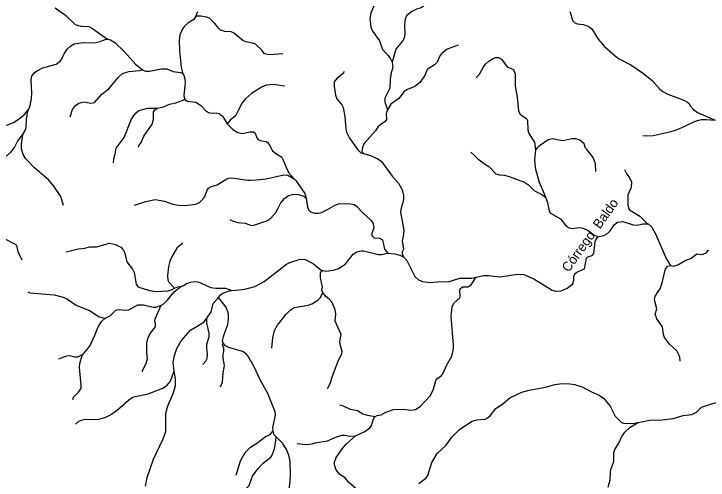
# Model space of a CAD drawing. Extents: x 473.9 to 500, y 7733.1 to 7760.8.
# Drawn here: x 487.72 to 494.97, y 7752.7 to 7757.57 of the extents above; entities that cross this region are included whole.
import ezdxf
from ezdxf.enums import TextEntityAlignment as Align

# ---------------------------------------------------------------- set-up
doc = ezdxf.new("R2010")
doc.units = 0
doc.header["$LTSCALE"] = 0.032
doc.layers.add('61', color=7, linetype='Continuous')
doc.layers.add('7', color=7, linetype='Continuous', lineweight=25)

msp = doc.modelspace()

# ---------------------------------------------------------------- linework, layer by layer
at = {"layer": '7'}
for points in [[(491.4328, 7757.94), (491.4295, 7757.9331), (491.4258, 7757.9254), (491.4287, 7757.8729), (491.4673, 7757.7937), (491.4875, 7757.7148), (491.481, 7757.6524), (491.4525, 7757.576), (491.4403, 7757.5199), (491.4523, 7757.4291), (491.4689, 7757.388), (491.5408, 7757.286), (491.5737, 7757.1962), (491.6292, 7757.1362), (491.653, 7757.1032), (491.6721, 7757.0618)], [(492.0601, 7757.6892), (491.9761, 7757.6316), (491.9275, 7757.6161), (491.8778, 7757.5911), (491.8233, 7757.5454), (491.8107, 7757.5127), (491.8042, 7757.4537), (491.8074, 7757.3614), (491.7987, 7757.3142), (491.7819, 7757.2829), (491.7129, 7757.1992), (491.6721, 7757.0618)], [(488.1564, 7757.6295), (488.2076, 7757.5922), (488.2622, 7757.5526), (488.3649, 7757.4568), (488.4241, 7757.4387), (488.5069, 7757.435), (488.5451, 7757.4161), (488.6674, 7757.3261), (488.7063, 7757.3039)], [(489.6379, 7757.5896), (489.636, 7757.5825), (489.6251, 7757.5419)], [(493.5277, 7757.5933), (493.561, 7757.4945), (493.5804, 7757.4738), (493.6057, 7757.4629), (493.6698, 7757.4565), (493.7198, 7757.4394), (493.7579, 7757.4112), (493.8247, 7757.3032), (493.8904, 7757.2251), (494.0045, 7757.126), (494.0454, 7757.097), (494.1642, 7757.0356), (494.2971, 7756.9448), (494.3878, 7756.8727), (494.468, 7756.7805), (494.5012, 7756.756), (494.5515, 7756.7299), (494.7189, 7756.6664), (494.7582, 7756.645), (494.7736, 7756.632), (494.7854, 7756.6081), (494.8159, 7756.5705), (494.8609, 7756.5353), (495.0451, 7756.4561)], [(489.6251, 7757.5419), (489.6033, 7757.5092), (489.5397, 7757.47), (489.5045, 7757.438), (489.4832, 7757.412), (489.455, 7757.348), (489.4494, 7757.2854), (489.4542, 7757.1797), (489.472, 7757.0096), (489.4873, 7756.9412)], [(490.5317, 7757.1489), (490.3917, 7757.14), (490.3552, 7757.1449), (490.3362, 7757.1537), (490.3155, 7757.1846), (490.2465, 7757.2502), (490.2146, 7757.2623), (490.1468, 7757.2752), (490.1127, 7757.2905), (490.0162, 7757.3684), (489.9938, 7757.3796), (489.9261, 7757.3845), (489.8822, 7757.3988), (489.8588, 7757.4182), (489.8236, 7757.4665), (489.766, 7757.5216), (489.7341, 7757.5344), (489.6756, 7757.5449), (489.6665, 7757.5444), (489.6251, 7757.5419)], [(487.8783, 7756.5705), (487.8933, 7756.609), (487.9075, 7756.685), (487.9107, 7756.7378), (487.9029, 7756.8789), (487.9125, 7756.9165), (487.9402, 7756.9537), (487.9653, 7756.9739), (488.0243, 7757.0027), (488.1654, 7757.042), (488.2072, 7757.0732), (488.2251, 7757.0971), (488.2473, 7757.1498), (488.2801, 7757.1982), (488.3194, 7757.2342), (488.3533, 7757.2554), (488.446, 7757.2682), (488.5614, 7757.2652), (488.6231, 7757.2775), (488.6784, 7757.3012), (488.7063, 7757.3039)], [(488.7063, 7757.3039), (488.7317, 7757.2978), (488.7786, 7757.268), (488.8793, 7757.1696), (488.9942, 7757.041), (489.0664, 7756.9839)], [(492.3631, 7757.2403), (492.2485, 7757.1976), (492.188, 7757.1501), (492.1701, 7757.1304), (492.1437, 7757.0639), (492.1151, 7757.0362), (492.0401, 7756.9847), (492.0155, 7756.9236), (491.9635, 7756.8511), (491.9118, 7756.807), (491.8344, 7756.779), (491.8007, 7756.7561), (491.7424, 7756.6829), (491.6582, 7756.6231), (491.6212, 7756.5564)], [(491.6721, 7757.0618), (491.6799, 7757.0055), (491.664, 7756.9502), (491.6535, 7756.8836), (491.6496, 7756.7918), (491.598, 7756.6874), (491.5974, 7756.6453), (491.619, 7756.5891), (491.6212, 7756.5564)], [(492.5492, 7756.8988), (492.5865, 7756.9373), (492.6286, 7757.0127), (492.6531, 7757.0443), (492.6835, 7757.0748), (492.7269, 7757.1026), (492.7519, 7757.1102), (492.7837, 7757.1103), (492.815, 7757.0952), (492.876, 7757.0143), (492.9391, 7756.9862), (492.9579, 7756.9387), (492.9588, 7756.8114), (492.9805, 7756.6975), (492.9926, 7756.555), (493.0059, 7756.5244), (493.031, 7756.5012), (493.075, 7756.476), (493.0862, 7756.4528), (493.0911, 7756.3556), (493.0995, 7756.3175), (493.1608, 7756.2267), (493.1703, 7756.1458)], [(489.0664, 7756.9839), (489.0975, 7756.9701), (489.1389, 7756.9687), (489.2622, 7756.9916), (489.3201, 7756.9918), (489.3857, 7756.9668), (489.4627, 7756.9532), (489.4873, 7756.9412)], [(488.3098, 7756.4908), (488.3348, 7756.5696), (488.3658, 7756.6115), (488.4009, 7756.6349), (488.4578, 7756.6485), (488.5287, 7756.6357), (488.5648, 7756.642), (488.6417, 7756.7284), (488.7139, 7756.7845), (488.8117, 7756.9016), (488.8595, 7756.9448), (488.9236, 7756.9666), (489.037, 7756.9754), (489.0664, 7756.9839)], [(489.4873, 7756.9412), (489.4996, 7756.9278), (489.5096, 7756.8887), (489.5111, 7756.8499), (489.4987, 7756.7156), (489.4982, 7756.7104), (489.5101, 7756.6735)], [(491.17, 7756.9652), (491.1661, 7756.9481), (491.0984, 7756.8944), (491.0687, 7756.8563), (491.0666, 7756.8133), (491.0819, 7756.7171), (491.0956, 7756.6814), (491.1489, 7756.6167), (491.1632, 7756.5876), (491.1804, 7756.493), (491.1884, 7756.3713), (491.198, 7756.3312), (491.2292, 7756.2695), (491.3148, 7756.146), (491.3456, 7756.1162), (491.3766, 7756.1093)], [(490.5505, 7756.8123), (490.4353, 7756.8296), (490.3613, 7756.8233), (490.3178, 7756.8064), (490.2044, 7756.7354), (490.1417, 7756.6808), (490.1088, 7756.639), (490.0633, 7756.5507), (490.0391, 7756.5039), (489.9838, 7756.4573), (489.9512, 7756.4186)], [(489.2203, 7756.5818), (489.2875, 7756.5978), (489.3481, 7756.6241), (489.413, 7756.6371), (489.5101, 7756.6735)], [(489.5101, 7756.6735), (489.5329, 7756.6558), (489.6234, 7756.6458), (489.6733, 7756.6121), (489.723, 7756.5584), (489.756, 7756.537), (489.7862, 7756.5315), (489.8354, 7756.5346), (489.8673, 7756.5256), (489.9007, 7756.4986), (489.9512, 7756.4186)], [(487.5421, 7756.3323), (487.5839, 7756.3541), (487.6324, 7756.397), (487.725, 7756.4345), (487.7822, 7756.4727), (487.8302, 7756.5142), (487.8783, 7756.5705)], [(487.818, 7756.3076), (487.8393, 7756.3437), (487.8507, 7756.3813), (487.855, 7756.4629), (487.8687, 7756.5547), (487.8783, 7756.5705)], [(488.7655, 7756.0124), (488.7663, 7756.057), (488.7815, 7756.1016), (488.7925, 7756.1652), (488.876, 7756.2754), (488.9472, 7756.4595), (488.9757, 7756.5068), (488.9991, 7756.5342), (489.0301, 7756.5562), (489.0801, 7756.5735), (489.1203, 7756.5827), (489.2203, 7756.5818)], [(489.0243, 7756.1755), (489.0279, 7756.1896), (489.0519, 7756.2226), (489.0794, 7756.2896), (489.1682, 7756.4165), (489.1807, 7756.4634), (489.1811, 7756.5437), (489.1922, 7756.5627), (489.2203, 7756.5818)], [(491.6212, 7756.5564), (491.6101, 7756.5274), (491.6148, 7756.4649), (491.6014, 7756.4435), (491.5288, 7756.3905), (491.4993, 7756.3467), (491.3811, 7756.2142), (491.3624, 7756.1719), (491.3585, 7756.1337), (491.3646, 7756.1178), (491.3766, 7756.1093)], [(489.9512, 7756.4186), (490.0109, 7756.358), (490.0634, 7756.3284), (490.1133, 7756.3182), (490.1866, 7756.3342), (490.2047, 7756.3345), (490.225, 7756.3349), (490.244, 7756.3226), (490.2619, 7756.2726), (490.2753, 7756.2541), (490.2943, 7756.2442), (490.3578, 7756.2339), (490.3693, 7756.2254), (490.3884, 7756.2023), (490.4249, 7756.1355), (490.4542, 7756.1109), (490.5204, 7756.0711), (490.5909, 7755.9117), (490.6489, 7755.8457)], [(494.2915, 7756.2975), (494.3194, 7756.2933), (494.399, 7756.2973), (494.5887, 7756.3391), (494.6419, 7756.3556), (494.7282, 7756.3955), (494.8372, 7756.4459), (494.9032, 7756.4639), (494.9549, 7756.4649), (495.0451, 7756.4561)], [(487.2806, 7755.6013), (487.308, 7755.6357), (487.3764, 7755.6837), (487.401, 7755.7106), (487.4524, 7755.8173), (487.5289, 7755.9153), (487.5856, 7756.0111), (487.6355, 7756.0725), (487.6956, 7756.1271), (487.7287, 7756.1707), (487.7652, 7756.2421), (487.818, 7756.3076)], [(488.2419, 7755.565), (488.2135, 7755.6605), (488.1402, 7755.7689), (488.0853, 7755.8324), (487.9389, 7755.958), (487.8455, 7756.0566), (487.8206, 7756.0977), (487.8018, 7756.1566), (487.8018, 7756.2074), (487.818, 7756.3076)], [(493.8019, 7755.9224), (493.7965, 7755.9997), (493.7721, 7756.0657), (493.7048, 7756.1514), (493.6941, 7756.165), (493.677, 7756.2113), (493.6348, 7756.2464), (493.5961, 7756.2634), (493.5498, 7756.2635), (493.4569, 7756.2428), (493.3945, 7756.2531), (493.3503, 7756.2604), (493.3023, 7756.2524), (493.2211, 7756.1959), (493.1883, 7756.1691), (493.1703, 7756.1458)], [(492.4961, 7756.122), (492.536, 7756.0834), (492.5667, 7756.0537), (492.6487, 7755.9922), (492.6835, 7755.9727), (492.7578, 7755.8979), (492.7917, 7755.8868), (492.8484, 7755.8811), (492.8959, 7755.8692), (493.0566, 7755.8105), (493.0963, 7755.7813), (493.1587, 7755.7188), (493.2381, 7755.6814), (493.2737, 7755.6513)], [(493.1703, 7756.1458), (493.1593, 7756.0427), (493.1653, 7755.9655), (493.1708, 7755.945), (493.184, 7755.8953), (493.2071, 7755.8089), (493.2553, 7755.7058), (493.2737, 7755.6513)], [(491.3766, 7756.1093), (491.4479, 7756.0873), (491.5246, 7756.0531), (491.5623, 7756.0236), (491.6744, 7755.8726), (491.7414, 7755.8004), (491.7784, 7755.7299), (491.7929, 7755.6739), (491.7913, 7755.6313), (491.785, 7755.592), (491.7826, 7755.5848), (491.7626, 7755.5246), (491.761, 7755.4949), (491.7962, 7755.3069), (491.7936, 7755.2638), (491.7786, 7755.1979), (491.7906, 7755.1078), (491.7778, 7755.0822), (491.7794, 7755.0588), (491.7952, 7755.0267)], [(494.1014, 7755.9421), (494.1243, 7755.8938), (494.1566, 7755.8522), (494.1719, 7755.8123), (494.1695, 7755.7524), (494.1342, 7755.6767), (494.1358, 7755.5689), (494.1452, 7755.5314), (494.1508, 7755.5205), (494.2595, 7755.4552), (494.3393, 7755.3745)], [(488.9829, 7755.5679), (489.1006, 7755.6085), (489.2002, 7755.6286), (489.2959, 7755.6094), (489.3825, 7755.5797), (489.4416, 7755.5707), (489.509, 7755.5669), (489.6227, 7755.5803), (489.6611, 7755.598), (489.6984, 7755.6308), (489.717, 7755.6604), (489.7417, 7755.7274), (489.7568, 7755.745), (489.7868, 7755.7627), (489.8469, 7755.7812), (489.9475, 7755.8443), (489.9669, 7755.8499), (489.9995, 7755.853), (490.1663, 7755.8307), (490.1937, 7755.8312), (490.2542, 7755.8323), (490.3597, 7755.8443), (490.5416, 7755.885), (490.5851, 7755.884), (490.6489, 7755.8457)], [(490.6489, 7755.8457), (490.6663, 7755.8258), (490.7615, 7755.6902), (490.7762, 7755.6408)], [(489.9783, 7755.4186), (490.0119, 7755.4007), (490.0624, 7755.3881), (490.139, 7755.3816), (490.2049, 7755.3576), (490.23, 7755.3598), (490.3652, 7755.4055), (490.4065, 7755.4343), (490.4602, 7755.4914), (490.4859, 7755.543), (490.5103, 7755.592), (490.5491, 7755.6371), (490.5906, 7755.6683), (490.6477, 7755.6831), (490.6958, 7755.68), (490.752, 7755.663), (490.7762, 7755.6408)], [(490.7762, 7755.6408), (490.7881, 7755.5476), (490.8028, 7755.5174), (490.8202, 7755.5006), (490.861, 7755.4859), (490.9002, 7755.4859), (490.9371, 7755.4935), (491.0002, 7755.5232), (491.07, 7755.5654), (491.1211, 7755.5861), (491.2369, 7755.5844), (491.2753, 7755.5747), (491.3005, 7755.5598), (491.3693, 7755.4838), (491.4501, 7755.4111), (491.4755, 7755.3787), (491.4802, 7755.3457), (491.4819, 7755.3339), (491.4627, 7755.2714), (491.4627, 7755.2505), (491.4869, 7755.227), (491.54, 7755.2228), (491.5716, 7755.2082), (491.5948, 7755.1077), (491.6291, 7755.0664)], [(493.2737, 7755.6513), (493.292, 7755.6077), (493.3178, 7755.4974), (493.3266, 7755.4846), (493.4321, 7755.4278), (493.4797, 7755.3627), (493.5009, 7755.3452), (493.5219, 7755.3326), (493.5565, 7755.3256), (493.6249, 7755.3367), (493.6672, 7755.3288), (493.7188, 7755.3038), (493.7804, 7755.2594), (493.8258, 7755.2399)], [(487.809, 7754.9939), (487.7694, 7755.083), (487.7589, 7755.1332), (487.7472, 7755.1538), (487.6124, 7755.2226), (487.5339, 7755.3268), (487.5145, 7755.3444), (487.4295, 7755.3946), (487.3523, 7755.4254), (487.3051, 7755.4693), (487.2734, 7755.5272), (487.2806, 7755.6013)], [(493.8258, 7755.2399), (493.8853, 7755.2524), (493.9236, 7755.2738), (493.9508, 7755.3024), (493.9944, 7755.3662), (494.0268, 7755.3904), (494.0812, 7755.3984), (494.1912, 7755.365), (494.2305, 7755.361), (494.2929, 7755.3752), (494.3393, 7755.3745)], [(494.3393, 7755.3745), (494.3479, 7755.3726), (494.3841, 7755.3386), (494.4276, 7755.2629), (494.5362, 7755.013), (494.5792, 7754.9397)], [(489.4834, 7755.1763), (489.4732, 7755.1601), (489.426, 7755.1184), (489.3795, 7755.0415), (489.3527, 7754.985), (489.3365, 7754.9268), (489.3283, 7754.8296), (489.3327, 7754.7841), (489.3424, 7754.766), (489.4012, 7754.7008)], [(492.5497, 7754.8163), (492.6284, 7754.8332), (492.6801, 7754.8332), (492.7932, 7754.8204), (492.8237, 7754.825), (492.9837, 7754.8492), (493.0497, 7754.8457), (493.1519, 7754.8008), (493.3459, 7754.6805), (493.3825, 7754.669), (493.4369, 7754.6751), (493.5003, 7754.7007), (493.562, 7754.7456), (493.5721, 7754.7848), (493.5706, 7754.824), (493.5811, 7754.8501), (493.602, 7754.8677), (493.6834, 7754.9031), (493.7016, 7755.0164), (493.7169, 7755.0305), (493.7623, 7755.0427), (493.7811, 7755.0645), (493.795, 7755.1889), (493.8049, 7755.2151), (493.8258, 7755.2399)], [(488.2689, 7755.0806), (488.3938, 7755.1123), (488.4661, 7755.12), (488.515, 7755.1339), (488.5861, 7755.1348), (488.7218, 7755.1715), (488.7842, 7755.1592), (488.8414, 7755.131), (488.8655, 7755.1022), (488.8781, 7755.0774), (488.9023, 7754.9757), (488.9615, 7754.8995), (488.9802, 7754.8656), (489.0017, 7754.7425), (489.0138, 7754.7212), (489.0274, 7754.7107), (489.1404, 7754.6769), (489.2092, 7754.6681), (489.3363, 7754.6752), (489.3761, 7754.6864), (489.4012, 7754.7008)], [(494.5792, 7754.9397), (494.6157, 7754.9311), (494.6563, 7754.9459), (494.7417, 7754.995), (494.7929, 7755.0111), (494.8564, 7755.0591), (494.9074, 7755.0547), (494.9575, 7755.0697), (494.978, 7755.103)], [(490.9494, 7754.885), (490.9845, 7754.8806), (491.0575, 7754.8885), (491.105, 7754.9053), (491.1579, 7754.9336), (491.1898, 7754.9589), (491.2653, 7755.0559), (491.305, 7755.0829), (491.3489, 7755.0923), (491.3741, 7755.0907), (491.5309, 7755.053), (491.5624, 7755.0522), (491.6291, 7755.0664)], [(491.6291, 7755.0664), (491.7032, 7755.0609), (491.7549, 7755.0472), (491.7952, 7755.0267)], [(489.9983, 7754.6785), (490.1123, 7754.6898), (490.1369, 7754.6922), (490.2403, 7754.7191), (490.3356, 7754.7718), (490.5712, 7754.9514), (490.605, 7754.9704), (490.7118, 7755.004), (490.7642, 7755.0006), (490.8151, 7754.9782), (490.854, 7754.9563), (490.9335, 7754.8916), (490.9494, 7754.885)], [(491.7952, 7755.0267), (491.827, 7754.9913), (491.9121, 7754.8222), (491.9483, 7754.7877), (491.9902, 7754.7706), (492.075, 7754.7626), (492.1814, 7754.7722), (492.26, 7754.7691), (492.3787, 7754.806), (492.5072, 7754.806), (492.5497, 7754.8163)], [(494.6827, 7753.941), (494.6791, 7753.986), (494.6479, 7754.0477), (494.5714, 7754.1178), (494.5174, 7754.1853), (494.5054, 7754.219), (494.4964, 7754.2979), (494.4387, 7754.3821), (494.4213, 7754.4304), (494.4371, 7754.4853), (494.4141, 7754.5795), (494.4198, 7754.619), (494.4596, 7754.6766), (494.4725, 7754.6953), (494.4941, 7754.7562), (494.5294, 7754.9039), (494.5516, 7754.9331), (494.5792, 7754.9397)], [(490.95, 7754.6565), (490.941, 7754.6818), (490.9478, 7754.7128), (490.9256, 7754.8101), (490.9253, 7754.8612), (490.9302, 7754.8714), (490.9494, 7754.885)], [(491.4958, 7753.3604), (491.5175, 7753.3707), (491.5604, 7753.3791), (491.6077, 7753.4052), (491.6871, 7753.4349), (491.7865, 7753.4381), (491.8686, 7753.4285), (491.918, 7753.4342), (491.9656, 7753.4656), (492.0713, 7753.5788), (492.1023, 7753.635), (492.128, 7753.7361), (492.1397, 7753.7533), (492.184, 7753.7852), (492.2035, 7753.8065), (492.2456, 7753.9009), (492.298, 7753.991), (492.3141, 7754.0676), (492.3157, 7754.1081), (492.2901, 7754.4077), (492.3016, 7754.5116), (492.3209, 7754.5474), (492.3799, 7754.6022), (492.3847, 7754.6215), (492.3799, 7754.6709), (492.3834, 7754.6947), (492.4077, 7754.7154), (492.4645, 7754.7169), (492.4983, 7754.7354), (492.5497, 7754.8163)], [(489.4657, 7754.721), (489.4957, 7754.7312), (489.5342, 7754.7533), (489.5708, 7754.7659), (489.6108, 7754.7707), (489.6401, 7754.7665), (489.6667, 7754.7601), (489.737, 7754.7259), (489.7815, 7754.7099), (489.8339, 7754.7026), (489.9325, 7754.7026), (489.9983, 7754.6785)], [(489.2619, 7754.5231), (489.2782, 7754.5301), (489.3286, 7754.5769), (489.3978, 7754.663), (489.4657, 7754.721)], [(489.4012, 7754.7008), (489.4355, 7754.7168), (489.4657, 7754.721)], [(489.8606, 7754.6054), (489.881, 7754.6321), (489.9065, 7754.6485), (489.975, 7754.6753), (489.9983, 7754.6785)], [(487.8696, 7754.6643), (487.8895, 7754.6545), (488.1439, 7754.631), (488.2384, 7754.6075), (488.2844, 7754.587), (488.3743, 7754.5261), (488.5195, 7754.4648), (488.6064, 7754.4076), (488.641, 7754.3945), (488.6757, 7754.3897)], [(489.7373, 7754.3874), (489.7847, 7754.455), (489.804, 7754.5402), (489.8606, 7754.6054)], [(489.9082, 7754.1267), (489.9035, 7754.149), (489.912, 7754.1979), (489.9376, 7754.2661), (489.9381, 7754.2675), (489.9586, 7754.3221), (489.9649, 7754.3775), (489.9633, 7754.4336), (489.9392, 7754.5045), (489.8606, 7754.6054)], [(490.4182, 7754.0741), (490.4259, 7754.1818), (490.445, 7754.2585), (490.4774, 7754.3171), (490.5643, 7754.428), (490.6093, 7754.4722), (490.6507, 7754.4993), (490.7962, 7754.5255), (490.8337, 7754.5396), (490.8985, 7754.5769), (490.927, 7754.6046), (490.95, 7754.6565)], [(490.9987, 7753.6524), (491.0297, 7753.7142), (491.0461, 7753.7775), (491.1093, 7753.9406), (491.1498, 7754.0193), (491.1531, 7754.0413), (491.1295, 7754.1123), (491.126, 7754.1439), (491.1419, 7754.2171), (491.0795, 7754.3586), (491.0843, 7754.4295), (491.0775, 7754.4767), (491.0461, 7754.554), (491.0194, 7754.5838), (490.9763, 7754.6172), (490.95, 7754.6565)], [(488.6757, 7754.3897), (488.7291, 7754.4143), (488.7877, 7754.4722), (488.8011, 7754.4773), (488.8283, 7754.4804), (488.887, 7754.4726), (488.923, 7754.4765), (489.0192, 7754.5269), (489.0778, 7754.527), (489.177, 7754.5047), (489.2077, 7754.5037), (489.2619, 7754.5231)], [(489.065, 7753.8283), (489.0654, 7753.8404), (489.1041, 7753.9166), (489.1199, 7753.9679), (489.1127, 7754.0275), (489.1135, 7754.1317), (489.1213, 7754.1752), (489.1455, 7754.227), (489.2039, 7754.2998), (489.2041, 7754.3326), (489.1953, 7754.3576), (489.1978, 7754.3819), (489.2619, 7754.5231)], [(488.4463, 7754.011), (488.5163, 7754.0958), (488.5697, 7754.2107), (488.6024, 7754.2969), (488.6369, 7754.355), (488.6757, 7754.3897)], [(489.3957, 7753.837), (489.3885, 7753.9203), (489.3965, 7753.9854), (489.3968, 7753.9881), (489.4252, 7754.0728), (489.4704, 7754.152), (489.5686, 7754.2629), (489.7078, 7754.3453), (489.7373, 7754.3874)], [(489.6957, 7753.9038), (489.7281, 7753.9384), (489.7404, 7753.969), (489.7445, 7754.0137), (489.7373, 7754.0752), (489.7389, 7754.1155), (489.7614, 7754.1935), (489.7628, 7754.2302), (489.7373, 7754.3355), (489.7373, 7754.3874)], [(489.8803, 7753.6696), (489.9008, 7753.7206), (489.9073, 7753.8172), (489.9232, 7753.8928), (489.9089, 7753.9705), (489.9073, 7754.0097), (489.9168, 7754.041), (489.9168, 7754.0731), (489.9024, 7754.111), (489.9082, 7754.1267)], [(490.4327, 7753.2109), (490.4289, 7753.2472), (490.454, 7753.3753), (490.4516, 7753.4092), (490.3753, 7753.6003), (490.295, 7753.7434), (490.2316, 7753.8813), (490.1659, 7753.9964), (490.1495, 7754.016), (490.1121, 7754.0415), (489.9668, 7754.0826), (489.9342, 7754.0995), (489.9082, 7754.1267)], [(488.1921, 7753.9627), (488.278, 7753.9961), (488.3068, 7753.9985), (488.3559, 7753.9843), (488.3923, 7753.9842), (488.4463, 7754.011)], [(488.3404, 7753.5392), (488.3453, 7753.5645), (488.3986, 7753.6156), (488.4263, 7753.6589), (488.4279, 7753.6888), (488.4087, 7753.8738), (488.4118, 7753.9165), (488.437, 7753.9973), (488.4463, 7754.011)], [(488.366, 7753.2827), (488.4017, 7753.3119), (488.4402, 7753.3283), (488.4714, 7753.3323), (488.596, 7753.3291), (488.6767, 7753.3519), (488.7332, 7753.3771), (488.8053, 7753.4315), (488.9194, 7753.5326), (488.9605, 7753.5597), (488.9902, 7753.5705), (489.1253, 7753.5978), (489.2796, 7753.6559), (489.3232, 7753.6871), (489.3589, 7753.7294), (489.3957, 7753.837)], [(489.0978, 7752.6322), (489.1167, 7752.7232), (489.1826, 7752.9159), (489.2833, 7753.1268), (489.309, 7753.204), (489.3106, 7753.3927), (489.3298, 7753.4744), (489.3874, 7753.6027), (489.4117, 7753.6834), (489.4117, 7753.7508), (489.3957, 7753.837)], [(491.953, 7752.6609), (492.0237, 7752.718), (492.046, 7752.7456), (492.0862, 7752.8794), (492.145, 7752.9755), (492.2369, 7753.0602), (492.2955, 7753.1468), (492.3786, 7753.2282), (492.5103, 7753.3117), (492.5585, 7753.3259), (492.6434, 7753.3328), (492.6698, 7753.3463), (492.6972, 7753.3687), (492.7564, 7753.4465), (492.8323, 7753.4989), (492.9013, 7753.5564), (493.0288, 7753.6141), (493.105, 7753.6378), (493.2752, 7753.6664), (493.3722, 7753.6955), (493.4494, 7753.7059), (493.5299, 7753.7043), (493.5825, 7753.6947), (493.597, 7753.6901), (493.656, 7753.6715), (493.7539, 7753.6174), (493.8354, 7753.5855), (493.8821, 7753.5535), (493.9493, 7753.4704), (494.0024, 7753.3635), (494.0683, 7753.2993), (494.0877, 7753.2931), (494.1815, 7753.2898), (494.2408, 7753.2987)], [(494.2408, 7753.2987), (494.3648, 7753.3234), (494.4938, 7753.3267), (494.6085, 7753.3411), (494.7107, 7753.3722), (494.8016, 7753.3837), (494.8507, 7753.4074), (494.9043, 7753.4605), (495.0892, 7753.5165), (495.1277, 7753.5223), (495.2944, 7753.52), (495.3752, 7753.5255)], [(491.1222, 7753.4829), (491.163, 7753.4724), (491.2343, 7753.4372), (491.3121, 7753.4227), (491.3659, 7753.3899), (491.4149, 7753.3747), (491.4958, 7753.3604)], [(491.2909, 7753.1607), (491.388, 7753.2061), (491.441, 7753.2433), (491.4577, 7753.2679), (491.4749, 7753.3264), (491.4958, 7753.3604)], [(493.9278, 7752.6245), (493.9488, 7752.6981), (493.9547, 7752.7762), (493.9572, 7752.8085), (493.989, 7752.8897), (493.9899, 7752.984), (494, 7753.0158), (494.0416, 7753.0831), (494.0717, 7753.1527), (494.1019, 7753.199), (494.158, 7753.2503), (494.2408, 7753.2987)], [(490.0464, 7752.7495), (490.0887, 7752.8984), (490.1403, 7752.9865), (490.1932, 7753.0397), (490.2723, 7753.0895), (490.3463, 7753.1487), (490.3989, 7753.1734), (490.4327, 7753.2109)], [(490.1257, 7752.5825), (490.1808, 7752.6398), (490.2143, 7752.7373), (490.2748, 7752.8186), (490.3281, 7752.873), (490.4074, 7752.937), (490.4215, 7752.9588), (490.4461, 7753.0279), (490.4572, 7753.0844), (490.4612, 7753.1473)], [(490.2469, 7752.0579), (490.2808, 7752.1147), (490.3075, 7752.1466), (490.3632, 7752.1879), (490.4689, 7752.2953), (490.5273, 7752.3771), (490.5709, 7752.4549), (490.592, 7752.5405), (490.6095, 7752.6857), (490.6112, 7752.7625), (490.6078, 7752.8904), (490.5948, 7752.9581), (490.5682, 7753.0238), (490.5298, 7753.0816), (490.4612, 7753.1473)], [(490.4612, 7753.1473), (490.4432, 7753.1687), (490.4327, 7753.2109)], [(490.6823, 7753.0808), (490.7704, 7753.0686), (490.8375, 7753.0774), (490.8693, 7753.0877), (490.997, 7753.106), (491.0937, 7753.1497), (491.1493, 7753.1654), (491.1791, 7753.1671), (491.2306, 7753.1575), (491.2909, 7753.1607)], [(491.1644, 7752.0963), (491.1858, 7752.1755), (491.2012, 7752.2098), (491.2269, 7752.2418), (491.3449, 7752.3536), (491.3649, 7752.3945), (491.368, 7752.4324), (491.3508, 7752.5182), (491.3173, 7752.5789), (491.3014, 7752.599), (491.29, 7752.6134), (491.222, 7752.6734), (491.1831, 7752.7195), (491.1264, 7752.757), (491.1058, 7752.7784), (491.084, 7752.8101), (491.0682, 7752.8725), (491.0895, 7752.934), (491.1537, 7753.0282), (491.1957, 7753.075), (491.2909, 7753.1607)]]:
    msp.add_lwpolyline(points, dxfattribs=at)

# ---------------------------------------------------------------- texts
at = {"layer": '61'}
msp.add_text('Córrego  Baldo', height=0.1, rotation=54.345, dxfattribs=at).set_placement((493.7795, 7755.2267), align=Align.CENTER)

doc.saveas('drawing.dxf')
